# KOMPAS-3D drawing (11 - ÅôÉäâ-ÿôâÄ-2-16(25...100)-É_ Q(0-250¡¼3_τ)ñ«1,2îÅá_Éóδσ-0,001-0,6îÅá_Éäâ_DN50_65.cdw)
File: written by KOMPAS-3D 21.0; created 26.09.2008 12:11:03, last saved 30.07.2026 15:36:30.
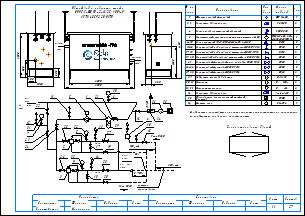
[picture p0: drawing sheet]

Sheets 1-2: A3, landscape

Document properties: Наименование: Макро:21; Автор: RaskoAdmin; Форматы листов документа: 2xA3; Полное имя файла: \\ur38nt01\Departments\КТО\КБ ПУРДГ\Заявки\Прайс-лист на типовые шкафы ГРПШ\ПУРДГ_стандарт_30_04_2026\ПУРДГ с РДГ(Н, В)\ПУРДГ-ШУГО-2-16(25...100)-Р_ Q(0-250нм3_ч)до1,2МПа_Рвых-0,001-0,6МПа_РДГ_DN50_65.cdw

Title block, sheet 1: Наименование: Пункт учета газа / ПУГ-Ш-400-Р / ЛГТИ.485922.001ТУ; designation: ЛГТИ.03.4411141; sheet number: 1; Количество листов документа: 2; organisation: ООО "ЭЛЬСТЕР Газэлектроника"; Форматы листов документа: A3; stored path: C:\Рабочие документы\Компас\ПУГ\Схема.cdw; Разработал: Устинов; Проверил: Кошкин; Утвердил: Кошкин
Title block, sheet 2: sheet number: 2; stored path: D:\Рабочие документы\Заявки\ПУРДГ\ПУРДГ-ШУЭО-2-100-Р 4411220.cdw; designation, second copy: ЛГТИ.03.4411141-

Views: Вид 1, Вид 2
Referenced files: wcvoit.frw
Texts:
  Normal
  № на
  схеме
  Усл.
  обозн.
  Марка
  (модель)
  Кол.
  Фильтр газовый фланцевый
  ФГ 16-50
  Регулятор давления газа
  РДГ-50
  Клапан предохранительный сбросной
  КПС DN20
  Измерительный комплекс с ротационным счетчиком Ду50
  СГ-ЭК-Р-(0,2...2,0)-
  Кран кнопочный VE-РАСКО-НЗ-1,6-G1/2-М20
  DN15
  Кран шаровой "под приварку" штуцерный DN20 PN16
  DN20
  Кран шаровой "под приварку" штуцерный DN15 PN16
  Кран шаровой "под приварку" штуцерный п/п DN20 PN16
  Кран шаровой фланцевый с мех. приводом DN50 PN16
  Кран шаровой фланцевый DN50 PN16
  Кран шаровой фланцевый DN65 PN16
  DN50
  DN65
  Индикатор перепада давления
  Манометр
  Манометр-напоромер
  Обогреватель газогорелочный шкафной
  (Эльтон")
  Счетчик газа
  Delta 15
  0...     МПа
  0...     кПа
  Venio-A-15
  ОГШН
  BK-G1,6
  Общий вид и габариты шкафа
  ПУРДГ-ШУГО-2-16(25...100)-Р
  Выход газа
  Вход газа
  logo-rasko-ge.png
  DN 1
  местное
  сопротивление
  Римп DN20
  Выход
  газа
  Р=     кПа
  Вход
  Р=       МПа
  PDI
  Схема открывания дверей
  Предприятие изготовитель может заменять комплектующие на аналогичные,
  не ухудшающие заявленных характеристик.
  Должность
  Конструктор
  Фамилия
  Подпись
  Дата
  Согласовано
  Максимкин
  Лист
  Листов
  POLYLINE_STYLE_0.18_RGB_0_0_0
  POLYLINE_STYLE_0.50_RGB_0_0_0
  POLYLINE_STYLE_0.34_RGB_0_0_0
  PHANTOM_RGB_0_0_0_SC_1_THICK_0.18
  K5LT_THIN_RGB_0_0_0_THICK_0.18
  K5LT32769_RGB_0_0_0_THICK_0.18
  K5LT12_RGB_0_0_0_SC_1_THICK_0.18
  K5LT_DASHED_RGB_0_0_0_SC_1_THICK_0.18
  ACISOTGL_RGB_0_0_0_SC_0.8_THICK_0.25
  CONTINUOUS_RGB_0_127_31_THICK_0.3
  CONTINUOUS_RGB_0_0_255_THICK_0.35
  CONTINUOUS_RGB_255_0_0_THICK_0.35
  POLYLINE_STYLE_0.25_RGB_0_0_0
  CONTINUOUS_RGB_0_0_0_THICK_0.5
  POLYLINE_STYLE_0.35_RGB_0_0_255
  CONTINUOUS_RGB_0_0_0_THICK_0.4
  CONTINUOUS_RGB_0_0_0_THICK_0.35
  НЕВИДИМАЯ_RGB_0_0_0_SC_0.3_THICK_0.25
  СONTINUOUS_RGB_0_0_0_THICK_0.25
  ОСЕВАЯ2_RGB_248_153_30_SC_0.3_THICK_0.25
  Без оформления
Dimensions and other numbers on the sheet: 1; 2, 3; 2; 4; 5; 6-10; 11-16; 17, 18; 19, 20; 21; 22-26; 27, 28; 29; 30, 31; 32, 33; 34; 35; 36; 1500; 250; 300; 1050; 550; 305; 2500; 4130; 2000; 2800; 5,,,7DN 1; 7; 31; 12; 22; 23; 24; 11; 6; 30; 25; 32; 8; 13; 27; 19; 10; 15; 26; 33; 9; 3; 14; 28; 20; 17; 18; 16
